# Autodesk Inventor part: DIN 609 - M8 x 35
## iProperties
CLASSIFICATION: 31161504
MANUFACTURER: DIN Système de normes
Author: robert
Shininess: 20.0
Angle Display Precision: 2
Document Length Units: 11269
Document Angle Units: 11283
Document Time Units: 11279
Document Mass Units: 11290
Document Length Units Precision: 3
Document Angle Units Precision: 2
Compacted: True
PropertySet Name: _Private Model Information
Created: 2002-06
Part Number: DIN 609 - M8 x 35
Material: Par défaut
Catalog Web Link: file:///C:/Program Files/Autodesk/Inventor 5/Content/Din/index.htm?doNavigateId=444F3037-BF83-11D4-A9EA-0080AD303E0A|3119B878B16811D4BA6900C04F798F98|true
Description: Vis ajustable à tête hexagonale
Document SubType Name: Standard Catalog Part
Standard: DIN 609 - M8 x 35
Designer: robert
Control State: 0
Master: False
Checked Out: False
PropertySet Name: Design Tracking Control
Density: 0.0
Volumn: 0.0
Area: 0.0
PropertySet Name: Model Information
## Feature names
1. Base1
